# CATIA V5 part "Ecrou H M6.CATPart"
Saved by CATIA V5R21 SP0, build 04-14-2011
Part number: Ecrou H M6
Material "Acier": density 7860 kg/m3, Young's modulus 2e+11 Pa, Poisson ratio 0.266, thermal expansion 1.17e-05 1/K
Bounding box of the stored display mesh (mm): x -4 to 4, y -4.619 to 4.619, z 0 to 3
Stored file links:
  C:\Users\Utilisateur\Desktop\Fichiers à télécharger dans l'ouvrage\Exercice 9 Pompe de ventilation.CATDrawing (corrigé)\Ecrou H M6.CATPart
  C:\Program Files\Dassault Systemes\B21\win_b64\startup\materials\French\Catalog.CATMaterial
  C:\Users\Utilisateur\Desktop\Fichiers à télécharger dans l'ouvrage\Exercice 9 Pompe de ventilation.CATDrawing (corrigé)\CATIA_EnvironmentMap_Satin_512x512.jpg
  C:\Users\Olivier\Desktop\redaction CATIA (local)\pompe à moteur de ventilation refait\Pompe_a_moteur_de_ventilation.CATProduct
  C:\Users\Olivier\Desktop\redaction CATIA (local)\pompe à moteur de ventilation refait\Ecrou a collerette M5.CATPart
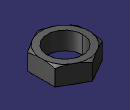
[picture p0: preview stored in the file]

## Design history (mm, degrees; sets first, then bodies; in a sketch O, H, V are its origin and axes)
Body1 (main body), material "Acier"
  Sketch1 on xy-plane, origin (0, 0, 0), H (1, 0, 0), V (0, 1, 0)
    circle A1 centre (0, 0) radius 3
    point P1 (4, -2.3094)
    point P2 (4, 2.3094)
    point P3 (0, 4.6188)
    point P4 (-4, 2.3094)
    point P5 (-4, -2.3094)
    point P6 (0, -4.6188)
    point P7 (4, 0)
    line L1 (4, -2.3094) -> (4, 2.3094)
    line L2 (4, 2.3094) -> (0, 4.6188)
    line L3 (0, 4.6188) -> (-4, 2.3094)
    line L4 (-4, 2.3094) -> (-4, -2.3094)
    line L5 (-4, -2.3094) -> (0, -4.6188)
    line L6 (0, -4.6188) -> (4, -2.3094)
    construction line L7 (0, 0) -> (4, 0)
    construction circle A2 centre (0, 0) radius 4.6188
    construction arc A3 centre (-4, -2.3094) radius 4.6188 from (-4, 2.3094) to (0, -4.6188) cw
    construction arc A4 centre (4, 2.3094) radius 4.6188 from (0, 4.6188) to (4, -2.3094) ccw
    distance L1 L4 = 8
    horizontal: L7 H
    coincidence: A2 P1, A2 P2, A2 P3, A2 P4, A2 P5, A2 P6, A3 O, A4 O
    midpoint: P7 L1
    parallelism: L1 L4
  Pad1: profile Sketch1, direction (0, 0, 1), length 3
  Sketch2 on yz-plane, origin (0, 0, 0), H (0, 1, 0), V (0, 0, 1)
    line L1 (3.8458, 3.1016) -> (4.7183, 2.6279)
    line L2 (4.7183, 2.6279) -> (4.7183, 3.1016)
    line L3 (4.7183, 3.1016) -> (3.8458, 3.1016)
    vertical: L2 V
    horizontal: L3 H
  Groove1: profile Sketch2, axis Sketch2.V, angle 360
